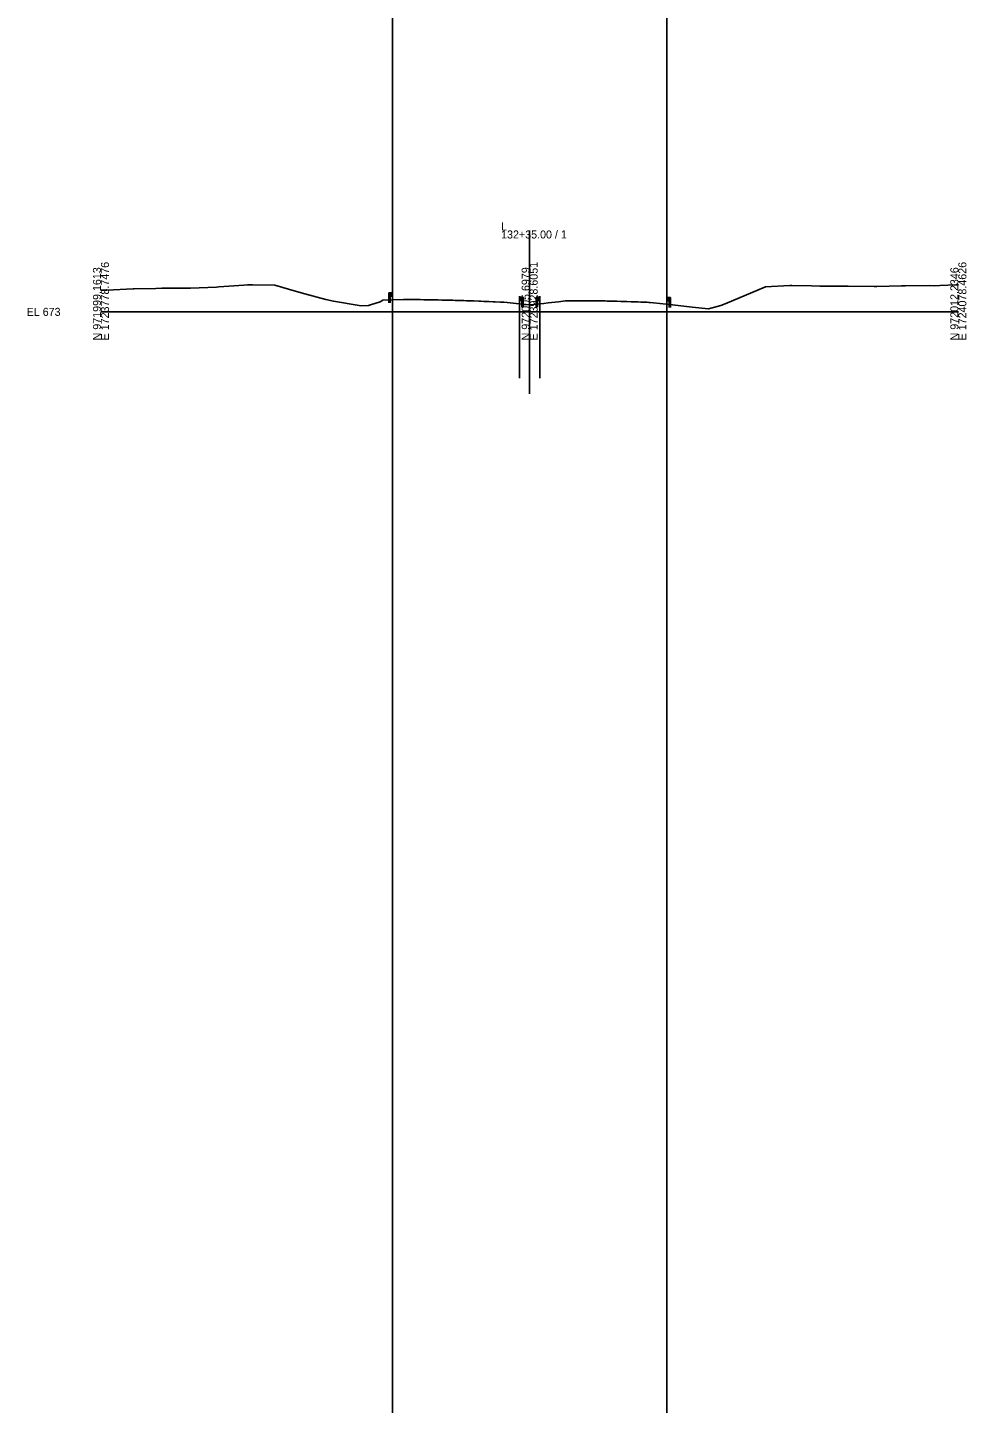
# Model space of a CAD drawing. Extents: x -26 to 303, y -29 to 15026.
# Drawn here: x -25.7 to 302.8, y 12617.9 to 13099.5 of the extents above; entities that cross this region are included whole.
import ezdxf

# ---------------------------------------------------------------- set-up
doc = ezdxf.new("R2010")
doc.units = 0
for name, color, linetype in [('Exist Cross Section Cell', 7, 'Continuous'), ('Exist XS Center Line Elevation Label', 7, 'Continuous'), ('Exist XS Ground Line', 7, 'Continuous'), ('Scratch_Level_0', 7, 'Continuous'), ('Typical Guardrail CELL', 7, 'Continuous')]:
    doc.layers.add(name, color=color, linetype=linetype)

msp = doc.modelspace()

# ---------------------------------------------------------------- linework, layer by layer
at = {"layer": 'Exist Cross Section Cell'}
for p, q in [((150, 13000), (150, 13028.48)), ((0, 13000), (150, 13000)), ((150, 13000), (300, 13000))]:
    msp.add_line(p, q, dxfattribs=at)
at = {"layer": 'Exist XS Ground Line'}
msp.add_lwpolyline([(0, 13007.6), (1.27, 13007.62), (2.01, 13007.63), (11.28, 13008), (11.6, 13008.01), (19.15, 13008.18), (21.28, 13008.24), (30.79, 13008.3), (31.29, 13008.3), (40.38, 13008.69), (41.3, 13008.76), (49.97, 13009.39), (51.31, 13009.42), (53.06, 13009.41), (60.86, 13009.36), (68.41, 13007.14), (71.33, 13006.35), (78.74, 13004.36), (81.34, 13003.71), (90.3, 13002.24), (90.96, 13002.13), (93.61, 13002.21), (94.35, 13002.48), (97.73, 13003.46), (98.67, 13004.04), (105.82, 13004.28), (107.69, 13004.35), (108.27, 13004.34), (108.95, 13004.33), (110.46, 13004.31), (111.39, 13004.32), (111.72, 13004.31), (112.98, 13004.26), (114.46, 13004.23), (115.47, 13004.21), (116.57, 13004.19), (117.97, 13004.16), (119.26, 13004.12), (120.47, 13004.08), (121.98, 13004.06), (123.11, 13004.03), (123.98, 13004.01), (125.45, 13003.96), (127.01, 13003.92), (127.95, 13003.89), (128.82, 13003.86), (130.45, 13003.81), (132.23, 13003.73), (132.94, 13003.7), (133.98, 13003.67), (135.66, 13003.6), (137.29, 13003.55), (137.93, 13003.53), (139.84, 13003.44), (140.62, 13003.39), (141.01, 13003.35), (142.16, 13003.23), (143.17, 13003.12), (145.25, 13002.91), (149.95, 13002.42), (154.99, 13002.97), (156.43, 13003.11), (160.07, 13003.52), (162.51, 13003.81), (163.2, 13003.82), (163.7, 13003.83), (164.25, 13003.84), (164.86, 13003.84), (165.53, 13003.84), (166.29, 13003.84), (168.02, 13003.84), (169.61, 13003.84), (170.53, 13003.84), (171.52, 13003.84), (173.02, 13003.82), (174.42, 13003.82), (175.53, 13003.82), (176.38, 13003.8), (177.07, 13003.79), (177.42, 13003.78), (178.01, 13003.77), (179.19, 13003.73), (180.51, 13003.68), (181.95, 13003.65), (183, 13003.63), (183.95, 13003.6), (185.51, 13003.54), (187.19, 13003.49), (188.01, 13003.47), (188.9, 13003.44), (189.31, 13003.43), (190.2, 13003.38), (190.52, 13003.36), (191.07, 13003.34), (191.69, 13003.32), (192.16, 13003.3), (193.28, 13003.18), (200.01, 13002.4), (206.88, 13001.65), (212.53, 13001.04), (215.59, 13001.89), (216.88, 13002.19), (218.36, 13002.86), (232.52, 13008.71), (241.07, 13009.17), (241.78, 13009.21), (248.61, 13009.06), (251.49, 13008.99), (260.96, 13009.02), (261.5, 13009.03), (270.55, 13008.89), (271.51, 13008.88), (280.14, 13009.05), (281.52, 13009.08), (289.73, 13009.24), (291.53, 13009.16), (293.49, 13009.17), (299.13, 13009.44), (300, 13009.49)], dxfattribs=at)
at = {"layer": 'Scratch_Level_0'}
for p, q in [((102, 15009.56), (102, -28.7)), ((198, 15009.56), (198, -28.7)), ((146.46, 13005.5), (146.46, 12976.8)), ((153.54, 13005.5), (153.54, 12976.8)), ((150, 13000), (150, 12971.3))]:
    msp.add_line(p, q, dxfattribs=at)
at = {"layer": 'Typical Guardrail CELL'}
for p, q in [((101.18, 13006.6), (100.68, 13006.6)), ((100.68, 13006.6), (100.68, 13004.11)), ((101.18, 13004.11), (100.68, 13004.11)), ((100.68, 13004.11), (100.68, 13003.1)), ((101.18, 13006.6), (101.18, 13004.11)), ((101.18, 13006.6), (101.68, 13006.6)), ((101.18, 13005.44), (101.68, 13005.44)), ((101.18, 13004.11), (101.18, 13003.1)), ((101.68, 13006.6), (101.68, 13005.44)), ((101.68, 13006.6), (101.97, 13006.39)), ((101.68, 13006.06), (101.97, 13006.27)), ((101.68, 13006.02), (101.68, 13006.06)), ((101.68, 13006.02), (101.68, 13005.97)), ((101.68, 13005.97), (101.97, 13005.77)), ((101.68, 13005.44), (101.97, 13005.64)), ((146.78, 13005.13), (146.49, 13004.93)), ((146.78, 13004.6), (146.49, 13004.8)), ((146.78, 13004.5), (146.49, 13004.3)), ((146.78, 13003.97), (146.49, 13004.17)), ((147.28, 13005.13), (146.78, 13005.13)), ((146.78, 13005.13), (146.78, 13003.97)), ((146.78, 13004.55), (146.78, 13004.6)), ((146.78, 13004.55), (146.78, 13004.5)), ((147.28, 13003.97), (146.78, 13003.97)), ((147.28, 13005.13), (147.28, 13002.64)), ((147.28, 13005.13), (147.78, 13005.13)), ((147.28, 13002.64), (147.78, 13002.64)), ((147.28, 13002.64), (147.28, 13001.64)), ((147.78, 13005.13), (147.78, 13002.64)), ((147.78, 13002.64), (147.78, 13001.64)), ((152.72, 13005.15), (152.22, 13005.15)), ((152.22, 13005.15), (152.22, 13002.67)), ((152.72, 13002.67), (152.22, 13002.67)), ((152.22, 13002.67), (152.22, 13001.66)), ((152.72, 13005.15), (152.72, 13002.67)), ((152.72, 13005.15), (153.22, 13005.15)), ((152.72, 13003.99), (153.22, 13003.99)), ((152.72, 13002.67), (152.72, 13001.66)), ((153.22, 13005.15), (153.22, 13003.99)), ((153.22, 13005.15), (153.51, 13004.95)), ((153.22, 13004.62), (153.51, 13004.82)), ((153.22, 13004.57), (153.22, 13004.62)), ((153.22, 13004.57), (153.22, 13004.52)), ((153.22, 13004.52), (153.51, 13004.32)), ((153.22, 13003.99), (153.51, 13004.19)), ((198.32, 13004.97), (198.03, 13004.77)), ((198.32, 13004.44), (198.03, 13004.64)), ((198.32, 13004.34), (198.03, 13004.14)), ((198.32, 13003.81), (198.03, 13004.01)), ((198.82, 13004.97), (198.32, 13004.97)), ((198.32, 13004.97), (198.32, 13003.81)), ((198.32, 13004.39), (198.32, 13004.44)), ((198.32, 13004.39), (198.32, 13004.34)), ((198.82, 13003.81), (198.32, 13003.81)), ((198.82, 13004.97), (198.82, 13002.48)), ((198.82, 13004.97), (199.32, 13004.97)), ((198.82, 13002.48), (199.32, 13002.48)), ((198.82, 13002.48), (198.82, 13001.48)), ((199.32, 13004.97), (199.32, 13002.48)), ((199.32, 13002.48), (199.32, 13001.48))]:
    msp.add_line(p, q, dxfattribs=at)
for centre, start, end in [((101.92, 13006.33), 304.9888, 54.997), ((101.92, 13005.7), 304.9634, 54.9941), ((146.54, 13004.86), 125.003, 235.0112), ((146.54, 13004.24), 125.0059, 235.0366), ((153.46, 13004.88), 304.9888, 54.997), ((153.46, 13004.26), 304.9634, 54.9941), ((198.08, 13004.7), 125.003, 235.0112), ((198.08, 13004.08), 125.0059, 235.0366)]:
    msp.add_arc(centre, 0.0776, start, end, dxfattribs=at)

# ---------------------------------------------------------------- texts
at = {"layer": 'Exist Cross Section Cell'}
for s, p in [('L', (140, 13028.48)), ('132+35.00 / 1', (140, 13025.68)), ('EL 673', (-26, 12998.6))]:
    msp.add_text(s, height=2.8, dxfattribs=at).set_placement(p)
for s, p in [('E 1723778.7476', (2.8, 12990)), ('E 1723928.6051', (152.8, 12990)), ('E 1724078.4626', (302.8, 12990)), ('N 971999.1613', (0, 12990)), ('N 972005.6979', (150, 12990)), ('N 972012.2346', (300, 12990))]:
    msp.add_text(s, height=2.8, rotation=90, dxfattribs=at).set_placement(p)
at = {"layer": 'Exist XS Center Line Elevation Label'}
msp.add_text('675.42', height=0.18, dxfattribs=at).set_placement((149.62, 13001.93))

doc.saveas('drawing.dxf')
